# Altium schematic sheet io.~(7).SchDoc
size Letter
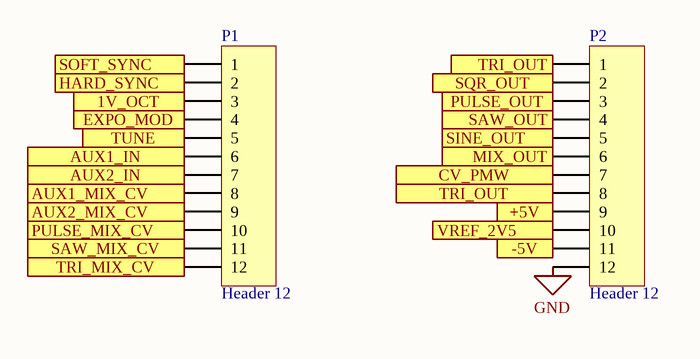
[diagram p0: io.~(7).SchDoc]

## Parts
P1  Header 12  [HDR1X12]
P2  Header 12  [HDR1X12]

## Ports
1V_OCT, +5V, -5V, AUX1_IN, AUX1_MIX_CV, AUX2_IN, AUX2_MIX_CV, CV_PMW, EXPO_MOD, HARD_SYNC, MIX_OUT, PULSE_MIX_CV, PULSE_OUT, SAW_MIX_CV, SAW_OUT, SINE_OUT, SOFT_SYNC, SQR_OUT, TRI_MIX_CV, TRI_OUT, TUNE, VREF_2V5

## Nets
GND: P2.12
1V_OCT: P1.3 ; port 1V_OCT
+5V: P2.9 ; port +5V
-5V: P2.11 ; port -5V
AUX1_IN: P1.6 ; port AUX1_IN
AUX1_MIX_CV: P1.8 ; port AUX1_MIX_CV
AUX2_IN: P1.7 ; port AUX2_IN
AUX2_MIX_CV: P1.9 ; port AUX2_MIX_CV
CV_PMW: P2.7 ; port CV_PMW
EXPO_MOD: P1.4 ; port EXPO_MOD
HARD_SYNC: P1.2 ; port HARD_SYNC
MIX_OUT: P2.6 ; port MIX_OUT
PULSE_MIX_CV: P1.10 ; port PULSE_MIX_CV
PULSE_OUT: P2.3 ; port PULSE_OUT
SAW_MIX_CV: P1.11 ; port SAW_MIX_CV
SAW_OUT: P2.4 ; port SAW_OUT
SINE_OUT: P2.5 ; port SINE_OUT
SOFT_SYNC: P1.1 ; port SOFT_SYNC
SQR_OUT: P2.2 ; port SQR_OUT
TRI_MIX_CV: P1.12 ; port TRI_MIX_CV
TRI_OUT: P2.1 P2.8 ; port TRI_OUT
TUNE: P1.5 ; port TUNE
VREF_2V5: P2.10 ; port VREF_2V5

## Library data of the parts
P1 P2 = Header 12: Header, 12-Pin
